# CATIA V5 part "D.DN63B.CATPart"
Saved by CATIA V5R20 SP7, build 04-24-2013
Part number: D.DN63B
Material "Nessuno"
Bounding box of the stored display mesh (mm): x -14.589 to 150.807, y -143.683 to 0, z -91.151 to 75.737
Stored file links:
  C:\Users\designer2\Desktop\Ottobre 2022\25-10-2022\04\Yori Evo 48V\D.DN63B.CATPart
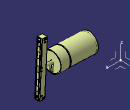
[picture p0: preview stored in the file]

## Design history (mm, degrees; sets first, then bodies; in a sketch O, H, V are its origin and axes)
AxisSystem1: origin (0, 0, 0), X (1, 0, 0), Y (0, 1, 0), Z (0, 0, 1)
Set1
  DatumSurface1
Body1 (main body), material "Nessuno"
